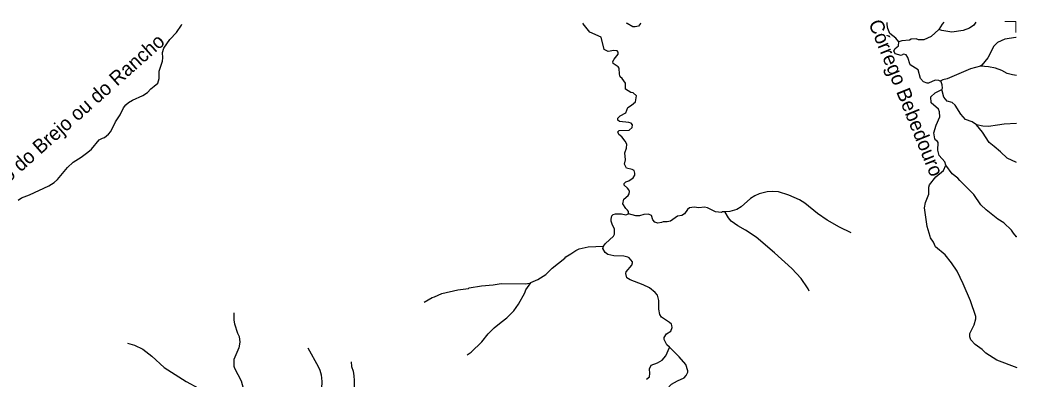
# Model space of a CAD drawing. Extents: x 393 to 446.6, y 8175.5 to 8231.
# Drawn here: x 435.29 to 446.51, y 8226.96 to 8231 of the extents above; entities that cross this region are included whole.
import ezdxf
from ezdxf.enums import TextEntityAlignment as Align

# ---------------------------------------------------------------- set-up
doc = ezdxf.new("R2010")
doc.units = 0
doc.header["$LTSCALE"] = 0.064
doc.linetypes.add('LONG_DASHED', pattern=[7.5, 6, -1.5])
doc.layers.add('61', color=7, linetype='Continuous')
for name, color, linetype, lineweight in [('63', 7, 'Continuous', 13), ('7', 7, 'Continuous', 25), ('9', 7, 'LONG_DASHED', 25)]:
    doc.layers.add(name, color=color, linetype=linetype, lineweight=lineweight)

msp = doc.modelspace()

# ---------------------------------------------------------------- linework, layer by layer
at = {"layer": '63'}
msp.add_lwpolyline([(446.4962, 8230.8623), (446.4962, 8230.9855), (446.3748, 8230.9855)], dxfattribs=at)
at = {"layer": '7'}
for points in [[(435.2654, 8228.9762), (435.305, 8229.0018), (435.396, 8229.0353), (435.6124, 8229.1371), (435.6705, 8229.1758), (435.7076, 8229.2097), (435.8206, 8229.3438), (435.8869, 8229.4035), (435.9757, 8229.4584), (436.0516, 8229.5149), (436.092, 8229.5505), (436.1792, 8229.6554), (436.2147, 8229.6748), (436.2389, 8229.6796), (436.2841, 8229.7168), (436.3115, 8229.7491), (436.3616, 8229.8573), (436.4133, 8229.9348), (436.452, 8230.0156), (436.4779, 8230.0479), (436.5086, 8230.0753), (436.5538, 8230.1011), (436.6717, 8230.1528), (436.7217, 8230.1851), (436.7605, 8230.2287), (436.7965, 8230.2581), (436.8396, 8230.2933), (436.8525, 8230.345), (436.8525, 8230.4257), (436.8896, 8230.5388), (436.8945, 8230.5775), (436.8896, 8230.6356), (436.9058, 8230.6873), (436.972, 8230.7826), (437.0479, 8230.8601), (437.1037, 8230.9452), (437.1098, 8230.9545)], [(442.1351, 8228.822), (442.1386, 8228.8324), (442.1363, 8228.8476), (442.1246, 8228.8627), (442.1087, 8228.8819), (442.0715, 8228.9337), (442.0845, 8228.9853), (442.1329, 8229.0289), (442.1458, 8229.0483), (442.1491, 8229.0725), (442.1412, 8229.0926), (442.1264, 8229.1096), (442.0877, 8229.1436), (442.0877, 8229.1613), (442.1087, 8229.1823), (442.1394, 8229.1936), (442.191, 8229.2259), (442.2072, 8229.255), (442.2072, 8229.2792), (442.2007, 8229.3083), (442.1781, 8229.3212), (442.1135, 8229.3357), (442.0925, 8229.3793), (442.1022, 8229.431), (442.0974, 8229.5085), (442.1135, 8229.5602), (442.1168, 8229.6038), (442.1006, 8229.6377), (442.0635, 8229.6877), (442.0263, 8229.7136), (442.0166, 8229.7426), (442.0312, 8229.7588), (442.1426, 8229.762), (442.1765, 8229.7911), (442.1813, 8229.8218), (442.1684, 8229.8411), (442.1394, 8229.8492), (442.036, 8229.8605), (442.0182, 8229.8751), (442.0183, 8229.8993), (442.0441, 8229.9235), (442.1087, 8229.9574), (442.1313, 8230.0172), (442.1717, 8230.043), (442.2169, 8230.0834), (442.2266, 8230.1496), (442.191, 8230.1819), (442.162, 8230.1851), (442.1022, 8230.2238), (442.1038, 8230.2933), (442.0667, 8230.345), (442.0424, 8230.3627), (442.0344, 8230.3934), (442.0328, 8230.4596), (442.0215, 8230.4742), (441.9649, 8230.5145), (441.9617, 8230.5355), (441.9746, 8230.563), (442.0215, 8230.6195), (442.0199, 8230.6389), (442.0086, 8230.6566), (441.9714, 8230.6598), (441.9084, 8230.6469), (441.8648, 8230.6711), (441.8293, 8230.81), (441.7001, 8230.8665), (441.6275, 8230.9602), (441.6265, 8230.9615), (441.6224, 8230.9668)], [(442.2756, 8230.9685), (442.272, 8230.9638), (442.2492, 8230.9344), (442.2137, 8230.9246), (442.1862, 8230.9246), (442.1208, 8230.9633), (442.1128, 8230.968)], [(444.6447, 8228.6065), (444.512, 8228.6705), (444.3743, 8228.7495), (444.2644, 8228.827), (444.1223, 8228.9433), (444.061, 8228.9788), (443.9415, 8229.0321), (443.8252, 8229.0676), (443.7606, 8229.0725), (443.696, 8229.0676), (443.6088, 8229.0483), (443.5572, 8229.0241), (443.512, 8228.9934), (443.4069, 8228.8997), (443.3553, 8228.8706), (443.2794, 8228.8464), (443.2253, 8228.8449)], [(441.8565, 8228.4562), (441.8794, 8228.488), (441.9682, 8228.5719), (441.9779, 8228.5913), (441.9811, 8228.651), (441.9553, 8228.6947), (441.9424, 8228.7399), (441.9407, 8228.7625), (441.9488, 8228.798), (441.9633, 8228.8141), (441.9892, 8228.8222), (442.0586, 8228.8206), (442.1071, 8228.8109), (442.1351, 8228.822)], [(443.2253, 8228.8449), (443.1985, 8228.8442), (443.1956, 8228.8431), (443.1825, 8228.8384), (443.1179, 8228.8432), (443.0259, 8228.89), (442.992, 8228.8981), (442.9274, 8228.8884), (442.8757, 8228.8949), (442.824, 8228.8884), (442.8014, 8228.8706), (442.7675, 8228.8206), (442.7385, 8228.8012), (442.6884, 8228.7948), (442.6093, 8228.7398), (442.5721, 8228.7302), (442.5352, 8228.731), (442.5278, 8228.7312), (442.5101, 8228.7224), (442.4688, 8228.7172), (442.4333, 8228.727), (442.4106, 8228.756), (442.3945, 8228.8012), (442.3622, 8228.8174), (442.3105, 8228.8141), (442.2589, 8228.798), (442.2201, 8228.798), (442.1351, 8228.822)], [(444.1711, 8227.9505), (444.1581, 8227.9771), (444.1524, 8227.9889), (444.0803, 8228.094), (443.9754, 8228.2054), (443.7816, 8228.3846), (443.5733, 8228.559), (443.4522, 8228.6397), (443.3666, 8228.6865), (443.2939, 8228.7382), (443.2616, 8228.7754), (443.2267, 8228.8422), (443.2253, 8228.8449)], [(441.0379, 8228.0483), (441.1156, 8228.0826), (441.2076, 8228.1408), (441.2771, 8228.2086), (441.4207, 8228.3232), (441.4321, 8228.3377), (441.4698, 8228.3614), (441.4861, 8228.3717), (441.5451, 8228.4088), (441.5823, 8228.4266), (441.684, 8228.4508), (441.8565, 8228.4562)], [(442.5988, 8227.3203), (442.5689, 8227.3495), (442.5382, 8227.4093), (442.5382, 8227.4302), (442.564, 8227.4706), (442.6125, 8227.5029), (442.627, 8227.5417), (442.6238, 8227.5659), (442.6206, 8227.5788), (442.5996, 8227.5998), (442.5075, 8227.6596), (442.4914, 8227.6903), (442.4801, 8227.7484), (442.4801, 8227.8453), (442.4623, 8227.9066), (442.4381, 8227.9357), (442.3735, 8227.9874), (442.3009, 8228.0245), (442.1555, 8228.0794), (442.1168, 8228.1004), (442.1071, 8228.1521), (442.1103, 8228.1682), (442.1749, 8228.2441), (442.1813, 8228.2716), (442.1813, 8228.2812), (442.1426, 8228.3248), (442.1313, 8228.3329), (442.0845, 8228.3442), (441.9714, 8228.3491), (441.9036, 8228.3652), (441.8729, 8228.3878), (441.8495, 8228.4318), (441.8565, 8228.4562)], [(439.8381, 8227.8295), (439.9271, 8227.8808), (439.9529, 8227.8872), (440.0369, 8227.926), (440.2145, 8227.9647), (440.3373, 8227.9825), (440.3437, 8227.989), (440.4826, 8228.0132), (440.615, 8228.0212), (440.7054, 8228.0374), (440.9735, 8228.0358), (441.0261, 8228.0431), (441.0379, 8228.0483)], [(440.3207, 8227.236), (440.3663, 8227.2655), (440.4842, 8227.3802), (440.5584, 8227.4706), (440.6231, 8227.5384), (440.7022, 8227.6046), (440.7668, 8227.6498), (440.8459, 8227.729), (440.8992, 8227.8065), (440.9718, 8227.9325), (440.9831, 8227.9647), (441.0371, 8228.0471), (441.0379, 8228.0483)], [(437.6961, 8227.706), (437.6954, 8227.6257), (437.7019, 8227.5837), (437.7342, 8227.4803), (437.7552, 8227.4416), (437.7633, 8227.377), (437.7503, 8227.3124), (437.6954, 8227.1832), (437.6954, 8227.1089), (437.7003, 8227.0863), (437.7778, 8226.941), (437.8068, 8226.8344), (437.8198, 8226.6923), (437.8131, 8226.5643)], [(436.496, 8227.3661), (436.578, 8227.3431), (436.6685, 8227.2978), (436.7718, 8227.2203), (436.909, 8227.0944), (437.1561, 8226.9361), (437.2982, 8226.8618), (437.5404, 8226.752), (437.6664, 8226.6777), (437.8131, 8226.5643)], [(438.5284, 8227.3127), (438.6449, 8227.1025), (438.6627, 8227.0637), (438.6756, 8227.012), (438.6837, 8226.9345), (438.6788, 8226.7731), (438.653, 8226.6697), (438.6368, 8226.5534), (438.6352, 8226.5018), (438.6415, 8226.4446)], [(442.3396, 8226.9619), (442.3751, 8226.9878), (442.3783, 8227.025), (442.3719, 8227.0766), (442.3929, 8227.1202), (442.4623, 8227.146), (442.5172, 8227.1767), (442.5576, 8227.2252), (442.5978, 8227.3179), (442.5988, 8227.3203)], [(442.4748, 8225.951), (442.4707, 8225.955), (442.4462, 8225.9931), (442.4316, 8226.0561), (442.4429, 8226.1239), (442.5124, 8226.2951), (442.535, 8226.4017), (442.5463, 8226.5438), (442.5398, 8226.6859), (442.5592, 8226.828), (442.5657, 8226.8441), (442.6205, 8226.907), (442.6868, 8226.9442), (442.7643, 8226.9781), (442.7853, 8227.004), (442.8047, 8227.0411), (442.8047, 8227.054), (442.782, 8227.1267), (442.7078, 8227.2139), (442.5988, 8227.3203)], [(439.0159, 8227.1564), (439.0194, 8227.1041), (439.0389, 8227.0508), (439.0454, 8226.9991), (439.0502, 8226.9475), (439.047, 8226.8377), (439.0325, 8226.7343), (439.005, 8226.631), (438.976, 8226.5534), (438.9663, 8226.5018), (438.9582, 8226.3597), (438.9695, 8226.2822), (438.9826, 8226.2386)]]:
    msp.add_lwpolyline(points, dxfattribs=at)
at = {"layer": '9'}
for points in [[(445.1801, 8230.7566), (445.148, 8230.7966), (445.079, 8230.8522), (445.0551, 8230.9062), (445.0477, 8230.9482), (445.0488, 8230.9739), (445.0489, 8230.9755)], [(446.0466, 8230.978), (446.0231, 8230.9445), (445.9761, 8230.9117), (445.9032, 8230.8843), (445.7758, 8230.8665), (445.6654, 8230.8829), (445.6313, 8230.8968)], [(445.6861, 8230.9771), (445.6853, 8230.9762), (445.6681, 8230.9561), (445.6313, 8230.8968)], [(445.6313, 8230.8968), (445.5428, 8230.8162), (445.4602, 8230.7784), (445.4022, 8230.7793), (445.3769, 8230.7889), (445.317, 8230.7885), (445.3017, 8230.7761), (445.2143, 8230.7684), (445.1801, 8230.7566)], [(445.6444, 8230.3134), (445.6287, 8230.3214), (445.5875, 8230.3246), (445.5136, 8230.2932), (445.4978, 8230.2926), (445.4589, 8230.3076), (445.4238, 8230.3442), (445.3962, 8230.4399), (445.3093, 8230.497), (445.2813, 8230.5812), (445.2641, 8230.6107), (445.2319, 8230.6177), (445.2049, 8230.6036), (445.1371, 8230.6206), (445.1221, 8230.6564), (445.1376, 8230.6802), (445.1774, 8230.7136), (445.1801, 8230.7566)], [(446.5018, 8230.8058), (446.498, 8230.8053), (446.3714, 8230.7871), (446.2906, 8230.7483), (446.249, 8230.7065), (446.1805, 8230.5752), (446.116, 8230.4952), (446.0986, 8230.4831)], [(446.0986, 8230.4831), (445.9864, 8230.4532), (445.7232, 8230.3404), (445.6736, 8230.3295), (445.6444, 8230.3134)], [(446.5028, 8230.3771), (446.4609, 8230.3843), (446.401, 8230.4009), (446.34, 8230.4332), (446.2699, 8230.4595), (446.1893, 8230.4773), (446.0986, 8230.4831)], [(445.664, 8230.2217), (445.6725, 8230.2373), (445.669, 8230.2716), (445.6555, 8230.3078), (445.6444, 8230.3134)], [(445.7094, 8229.3678), (445.697, 8229.407), (445.6343, 8229.4788), (445.6177, 8229.5368), (445.6241, 8229.6233), (445.6062, 8229.6482), (445.5971, 8229.65), (445.5839, 8229.6653), (445.5743, 8229.7323), (445.6009, 8229.8188), (445.6412, 8229.9138), (445.6368, 8229.9703), (445.6253, 8230.0009), (445.5437, 8230.0687), (445.5409, 8230.1371), (445.5904, 8230.1828), (445.664, 8230.2217)], [(446.0539, 8229.8215), (446.0041, 8229.8552), (445.9305, 8229.8837), (445.8796, 8229.9439), (445.8158, 8230.0458), (445.7788, 8230.0733), (445.7226, 8230.09), (445.6866, 8230.1335), (445.664, 8230.2217)], [(446.5041, 8229.8374), (446.3644, 8229.8313), (446.2905, 8229.8197), (446.19, 8229.804), (446.127, 8229.8073), (446.0539, 8229.8215)], [(446.5052, 8229.3985), (446.3991, 8229.4469), (446.3258, 8229.5185), (446.2534, 8229.5783), (446.1965, 8229.6254), (446.1229, 8229.7394), (446.0539, 8229.8215)], [(446.5108, 8227.0873), (446.285, 8227.1766), (446.1591, 8227.2539), (446.1165, 8227.2959), (446.0399, 8227.352), (445.9895, 8227.4056), (445.9793, 8227.439), (445.9809, 8227.4762), (446.0298, 8227.5739), (446.0476, 8227.6395), (446.0477, 8227.6682), (445.9856, 8227.8437), (445.9049, 8228.0343), (445.8352, 8228.1748), (445.7738, 8228.2721), (445.7033, 8228.3616), (445.5932, 8228.4487), (445.5702, 8228.5038), (445.5364, 8228.5506), (445.5319, 8228.5658), (445.4979, 8228.6791), (445.4707, 8228.8909), (445.4805, 8228.9504), (445.5186, 8229.0426), (445.5174, 8229.1202), (445.5245, 8229.149), (445.596, 8229.2382), (445.6812, 8229.3091), (445.7094, 8229.3678)], [(446.5073, 8228.5617), (446.5056, 8228.5642), (446.4704, 8228.603), (446.449, 8228.6381), (446.3608, 8228.7215), (446.2936, 8228.7628), (446.1634, 8228.8658), (446.1043, 8228.9233), (446.026, 8229.0386), (445.8677, 8229.1983), (445.8441, 8229.2221), (445.78, 8229.2719), (445.7094, 8229.3678)]]:
    msp.add_lwpolyline(points, dxfattribs=at)

# ---------------------------------------------------------------- texts
at = {"layer": '61'}
for s, rotation, p in [('Córrego Bebedouro', 292.013, (445.1879, 8230.0972)), ('Córrego do Brejo ou do Rancho', 41.622, (435.8013, 8229.7372))]:
    msp.add_text(s, height=0.16, rotation=rotation, dxfattribs=at).set_placement(p, align=Align.CENTER)

doc.saveas('drawing.dxf')
